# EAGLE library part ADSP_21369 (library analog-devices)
SHARC Processor Auto generated by make-symbol-device-package-bsdl.ulp Rev. 33 Source: 43623621369_208pinMQFP_bsdl_PrA_0106.txt http://www.analog.com/static/imported-files/data_sheets/ADSP-21367_21368_21369.pdf
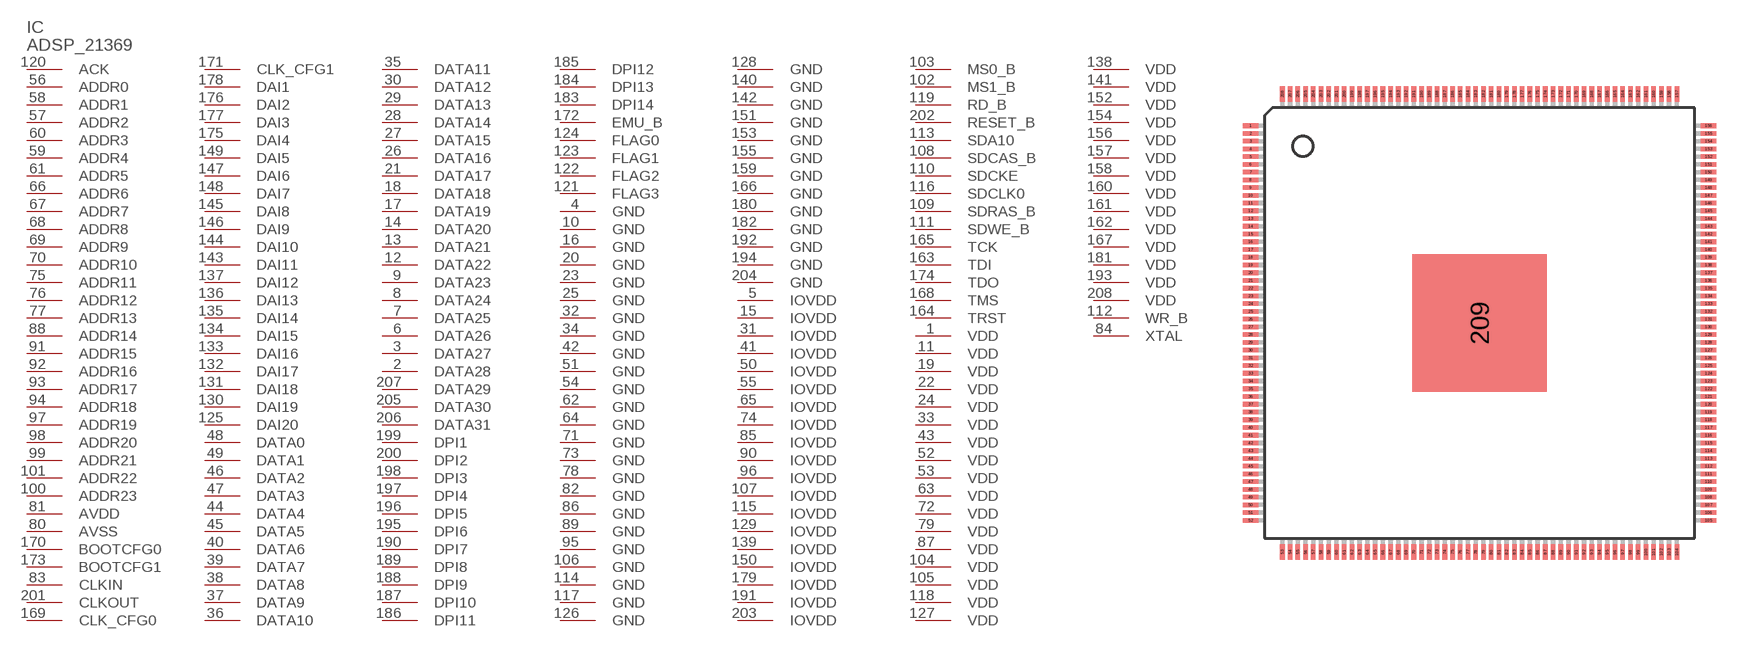
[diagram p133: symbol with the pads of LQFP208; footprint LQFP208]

Designator prefix IC

## ADSP_21369 (OC_FARNELL: unknown; OC_NEWARK: unknown)  [LQFP208]
1  VDD  pwr
2  DATA28
3  DATA27
4  GND  pwr
5  IOVDD  pwr
6  DATA26
7  DATA25
8  DATA24
9  DATA23
10  GND  pwr
11  VDD  pwr
12  DATA22
13  DATA21
14  DATA20
15  IOVDD  pwr
16  GND  pwr
17  DATA19
18  DATA18
19  VDD  pwr
20  GND  pwr
21  DATA17
22  VDD  pwr
23  GND  pwr
24  VDD  pwr
25  GND  pwr
26  DATA16
27  DATA15
28  DATA14
29  DATA13
30  DATA12
31  IOVDD  pwr
32  GND  pwr
33  VDD  pwr
34  GND  pwr
35  DATA11
36  DATA10
37  DATA9
38  DATA8
39  DATA7
40  DATA6
41  IOVDD  pwr
42  GND  pwr
43  VDD  pwr
44  DATA4
45  DATA5
46  DATA2
47  DATA3
48  DATA0
49  DATA1
50  IOVDD  pwr
51  GND  pwr
52  VDD  pwr
53  VDD  pwr
54  GND  pwr
55  IOVDD  pwr
56  ADDR0  out
57  ADDR2  out
58  ADDR1  out
59  ADDR4  out
60  ADDR3  out
61  ADDR5  out
62  GND  pwr
63  VDD  pwr
64  GND  pwr
65  IOVDD  pwr
66  ADDR6  out
67  ADDR7  out
68  ADDR8  out
69  ADDR9  out
70  ADDR10  out
71  GND  pwr
72  VDD  pwr
73  GND  pwr
74  IOVDD  pwr
75  ADDR11  out
76  ADDR12  out
77  ADDR13  out
78  GND  pwr
79  VDD  pwr
80  AVSS  pwr
81  AVDD  pwr
82  GND  pwr
83  CLKIN  in
84  XTAL  out
85  IOVDD  pwr
86  GND  pwr
87  VDD  pwr
88  ADDR14  out
89  GND  pwr
90  IOVDD  pwr
91  ADDR15  out
92  ADDR16  out
93  ADDR17  out
94  ADDR18  out
95  GND  pwr
96  IOVDD  pwr
97  ADDR19  out
98  ADDR20  out
99  ADDR21  out
100  ADDR23  out
101  ADDR22  out
102  MS1_B  out
103  MS0_B  out
104  VDD  pwr
105  VDD  pwr
106  GND  pwr
107  IOVDD  pwr
108  SDCAS_B  out
109  SDRAS_B  out
110  SDCKE  out
111  SDWE_B  out
112  WR_B  out
113  SDA10  out
114  GND  pwr
115  IOVDD  pwr
116  SDCLK0
117  GND  pwr
118  VDD  pwr
119  RD_B  out
120  ACK  in
121  FLAG3
122  FLAG2
123  FLAG1
124  FLAG0
125  DAI20
126  GND  pwr
127  VDD  pwr
128  GND  pwr
129  IOVDD  pwr
130  DAI19
131  DAI18
132  DAI17
133  DAI16
134  DAI15
135  DAI14
136  DAI13
137  DAI12
138  VDD  pwr
139  IOVDD  pwr
140  GND  pwr
141  VDD  pwr
142  GND  pwr
143  DAI11
144  DAI10
145  DAI8
146  DAI9
147  DAI6
148  DAI7
149  DAI5
150  IOVDD  pwr
151  GND  pwr
152  VDD  pwr
153  GND  pwr
154  VDD  pwr
155  GND  pwr
156  VDD  pwr
157  VDD  pwr
158  VDD  pwr
159  GND  pwr
160  VDD  pwr
161  VDD  pwr
162  VDD  pwr
163  TDI  in
164  TRST  in
165  TCK  in
166  GND  pwr
167  VDD  pwr
168  TMS  in
169  CLK_CFG0  in
170  BOOTCFG0  in
171  CLK_CFG1  in
172  EMU_B  out
173  BOOTCFG1  in
174  TDO  out
175  DAI4
176  DAI2
177  DAI3
178  DAI1
179  IOVDD  pwr
180  GND  pwr
181  VDD  pwr
182  GND  pwr
183  DPI14
184  DPI13
185  DPI12
186  DPI11
187  DPI10
188  DPI9
189  DPI8
190  DPI7
191  IOVDD  pwr
192  GND  pwr
193  VDD  pwr
194  GND  pwr
195  DPI6
196  DPI5
197  DPI4
198  DPI3
199  DPI1
200  DPI2
201  CLKOUT  out
202  RESET_B  in
203  IOVDD  pwr
204  GND  pwr
205  DATA30
206  DATA31
207  DATA29
208  VDD  pwr

## Footprint LQFP208 (pad centres in mm)
LQFP208 COMPLIANT TO JEDEC STANDARDS MS-026-BJB-HD Auto generated by make-symbol-device-package-bsdl.ulp Rev. 26 Source: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
smd 1 x 0.3: 1 -14.8,12.75; 2 -14.8,12.25; 3 -14.8,11.75; 4 -14.8,11.25; 5 -14.8,10.75; 6 -14.8,10.25; 7 -14.8,9.75; 8 -14.8,9.25; 9 -14.8,8.75; 10 -14.8,8.25; 11 -14.8,7.75; 12 -14.8,7.25; 13 -14.8,6.75; 14 -14.8,6.25; 15 -14.8,5.75; 16 -14.8,5.25; 17 -14.8,4.75; 18 -14.8,4.25; 19 -14.8,3.75; 20 -14.8,3.25; 21 -14.8,2.75; 22 -14.8,2.25; 23 -14.8,1.75; 24 -14.8,1.25; 25 -14.8,0.75; 26 -14.8,0.25; 27 -14.8,-0.25; 28 -14.8,-0.75; 29 -14.8,-1.25; 30 -14.8,-1.75; 31 -14.8,-2.25; 32 -14.8,-2.75; 33 -14.8,-3.25; 34 -14.8,-3.75; 35 -14.8,-4.25; 36 -14.8,-4.75; 37 -14.8,-5.25; 38 -14.8,-5.75; 39 -14.8,-6.25; 40 -14.8,-6.75; 41 -14.8,-7.25; 42 -14.8,-7.75; 43 -14.8,-8.25; 44 -14.8,-8.75; 45 -14.8,-9.25; 46 -14.8,-9.75; 47 -14.8,-10.25; 48 -14.8,-10.75; 49 -14.8,-11.25; 50 -14.8,-11.75; 51 -14.8,-12.25; 52 -14.8,-12.75; 105 14.8,-12.75; 106 14.8,-12.25; 107 14.8,-11.75; 108 14.8,-11.25; 109 14.8,-10.75; 110 14.8,-10.25; 111 14.8,-9.75; 112 14.8,-9.25; 113 14.8,-8.75; 114 14.8,-8.25; 115 14.8,-7.75; 116 14.8,-7.25; 117 14.8,-6.75; 118 14.8,-6.25; 119 14.8,-5.75; 120 14.8,-5.25; 121 14.8,-4.75; 122 14.8,-4.25; 123 14.8,-3.75; 124 14.8,-3.25; 125 14.8,-2.75; 126 14.8,-2.25; 127 14.8,-1.75; 128 14.8,-1.25; 129 14.8,-0.75; 130 14.8,-0.25; 131 14.8,0.25; 132 14.8,0.75; 133 14.8,1.25; 134 14.8,1.75; 135 14.8,2.25; 136 14.8,2.75; 137 14.8,3.25; 138 14.8,3.75; 139 14.8,4.25; 140 14.8,4.75; 141 14.8,5.25; 142 14.8,5.75; 143 14.8,6.25; 144 14.8,6.75; 145 14.8,7.25; 146 14.8,7.75; 147 14.8,8.25; 148 14.8,8.75; 149 14.8,9.25; 150 14.8,9.75; 151 14.8,10.25; 152 14.8,10.75; 153 14.8,11.25; 154 14.8,11.75; 155 14.8,12.25; 156 14.8,12.75
smd 0.3 x 1: 53 -12.75,-14.8; 54 -12.25,-14.8; 55 -11.75,-14.8; 56 -11.25,-14.8; 57 -10.75,-14.8; 58 -10.25,-14.8; 59 -9.75,-14.8; 60 -9.25,-14.8; 61 -8.75,-14.8; 62 -8.25,-14.8; 63 -7.75,-14.8; 64 -7.25,-14.8; 65 -6.75,-14.8; 66 -6.25,-14.8; 67 -5.75,-14.8; 68 -5.25,-14.8; 69 -4.75,-14.8; 70 -4.25,-14.8; 71 -3.75,-14.8; 72 -3.25,-14.8; 73 -2.75,-14.8; 74 -2.25,-14.8; 75 -1.75,-14.8; 76 -1.25,-14.8; 77 -0.75,-14.8; 78 -0.25,-14.8; 79 0.25,-14.8; 80 0.75,-14.8; 81 1.25,-14.8; 82 1.75,-14.8; 83 2.25,-14.8; 84 2.75,-14.8; 85 3.25,-14.8; 86 3.75,-14.8; 87 4.25,-14.8; 88 4.75,-14.8; 89 5.25,-14.8; 90 5.75,-14.8; 91 6.25,-14.8; 92 6.75,-14.8; 93 7.25,-14.8; 94 7.75,-14.8; 95 8.25,-14.8; 96 8.75,-14.8; 97 9.25,-14.8; 98 9.75,-14.8; 99 10.25,-14.8; 100 10.75,-14.8; 101 11.25,-14.8; 102 11.75,-14.8; 103 12.25,-14.8; 104 12.75,-14.8; 157 12.75,14.8; 158 12.25,14.8; 159 11.75,14.8; 160 11.25,14.8; 161 10.75,14.8; 162 10.25,14.8; 163 9.75,14.8; 164 9.25,14.8; 165 8.75,14.8; 166 8.25,14.8; 167 7.75,14.8; 168 7.25,14.8; 169 6.75,14.8; 170 6.25,14.8; 171 5.75,14.8; 172 5.25,14.8; 173 4.75,14.8; 174 4.25,14.8; 175 3.75,14.8; 176 3.25,14.8; 177 2.75,14.8; 178 2.25,14.8; 179 1.75,14.8; 180 1.25,14.8; 181 0.75,14.8; 182 0.25,14.8; 183 -0.25,14.8; 184 -0.75,14.8; 185 -1.25,14.8; 186 -1.75,14.8; 187 -2.25,14.8; 188 -2.75,14.8; 189 -3.25,14.8; 190 -3.75,14.8; 191 -4.25,14.8; 192 -4.75,14.8; 193 -5.25,14.8; 194 -5.75,14.8; 195 -6.25,14.8; 196 -6.75,14.8; 197 -7.25,14.8; 198 -7.75,14.8; 199 -8.25,14.8; 200 -8.75,14.8; 201 -9.25,14.8; 202 -9.75,14.8; 203 -10.25,14.8; 204 -10.75,14.8; 205 -11.25,14.8; 206 -11.75,14.8; 207 -12.25,14.8; 208 -12.75,14.8
smd 8.712 x 8.89: 209 0,0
